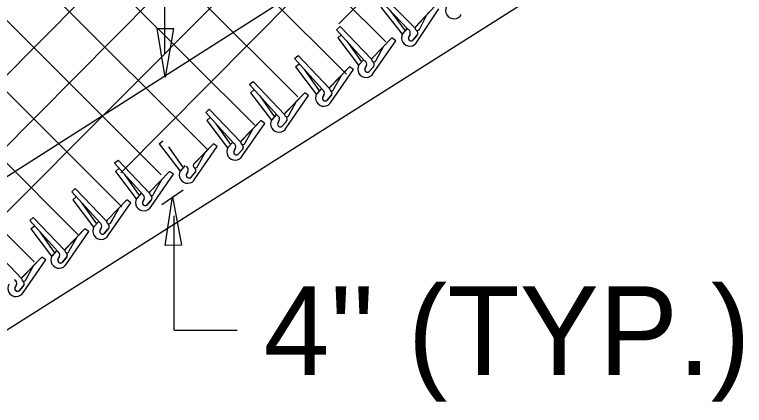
# Model space of a CAD drawing. Extents: x 0 to 2.85, y -0.1 to 1.83.
# Drawn here: x 1.6771 to 1.7594, y 1.3819 to 1.426 of the extents above; entities that cross this region are included whole.
import ezdxf

# ---------------------------------------------------------------- set-up
doc = ezdxf.new("R2010")
doc.units = 0
for name, color, linetype in [('CT_Dimensions', 7, 'Continuous'), ('sb_Chainlink Fence', 7, 'Continuous'), ('sb_Earth', 7, 'Continuous'), ('sb_Existing Structural Steel', 7, 'Continuous')]:
    doc.layers.add(name, color=color, linetype=linetype)

msp = doc.modelspace()

# ---------------------------------------------------------------- linework, layer by layer
at = {"layer": 'CT_Dimensions'}
for p, q in [((1.694051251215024, 1.4215621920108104), (1.694051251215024, 1.43019635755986)), ((1.6937099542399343, 1.404569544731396), (1.696140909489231, 1.4062363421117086)), ((1.6950964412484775, 1.390403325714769), (1.6950964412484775, 1.4033021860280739)), ((1.6950964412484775, 1.390403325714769), (1.702206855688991, 1.390403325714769))]:
    msp.add_line(p, q, dxfattribs=at)
for points in [[(1.6950225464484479, 1.4244544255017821), (1.6941064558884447, 1.4189578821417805), (1.6931903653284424, 1.4244544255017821)], [(1.694091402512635, 1.399944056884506), (1.6949236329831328, 1.4054539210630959), (1.6959233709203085, 1.3999719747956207)]]:
    msp.add_lwpolyline(points, close=True, dxfattribs=at)
at = {"layer": 'sb_Chainlink Fence'}
for p, q in [((1.6886284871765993, 1.4161145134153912), (1.9989168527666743, 1.728697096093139)), ((1.6483040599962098, 1.3830225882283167), (1.9873022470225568, 1.7249794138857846)), ((1.689092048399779, 1.4081735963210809), (1.9986754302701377, 1.720458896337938)), ((1.713665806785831, 1.4249653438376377), (1.998677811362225, 1.7124648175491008)), ((1.6649561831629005, 1.4078165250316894), (1.9657124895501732, 1.7111977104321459)), ((1.6426948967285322, 1.4992079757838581), (1.7189591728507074, 1.422943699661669)), ((1.6378194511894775, 1.4960224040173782), (1.714540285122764, 1.4193015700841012)), ((1.6330927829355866, 1.4926880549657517), (1.7090524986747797, 1.4167283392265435)), ((1.6282212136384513, 1.4894986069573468), (1.70419564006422, 1.4135241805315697)), ((1.623474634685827, 1.486184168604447), (1.6988537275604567, 1.4108050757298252)), ((1.6186308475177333, 1.4829669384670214), (1.6936570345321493, 1.4079407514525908)), ((1.6138328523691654, 1.4797039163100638), (1.6892080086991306, 1.404328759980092)), ((1.609050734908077, 1.4764250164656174), (1.6843031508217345, 1.4011726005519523)), ((1.604244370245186, 1.47317036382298), (1.6793177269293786, 1.3980970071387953)), ((1.7214957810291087, 1.4243386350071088), (1.7182739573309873, 1.4277686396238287)), ((1.7222936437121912, 1.4244802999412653), (1.7186701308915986, 1.428126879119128)), ((1.7184073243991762, 1.4268425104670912), (1.7208169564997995, 1.4238052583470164)), ((1.7245110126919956, 1.4269648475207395), (1.7223387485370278, 1.4246297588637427)), ((1.7245110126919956, 1.4269648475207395), (1.722352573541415, 1.4246434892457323)), ((1.7194459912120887, 1.4265093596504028), (1.7211406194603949, 1.4241976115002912)), ((1.7225162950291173, 1.4229733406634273), (1.7249566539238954, 1.426659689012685)), ((1.7227952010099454, 1.424428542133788), (1.7236084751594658, 1.4259792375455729)), ((1.7134325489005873, 1.4243088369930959), (1.7138360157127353, 1.4246588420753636)), ((1.7165830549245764, 1.4208132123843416), (1.7134325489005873, 1.4243088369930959)), ((1.7173836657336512, 1.4209384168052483), (1.7138360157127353, 1.4246588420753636)), ((1.7213541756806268, 1.4244253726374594), (1.7208624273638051, 1.4238465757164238)), ((1.7213607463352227, 1.4244343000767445), (1.7208649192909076, 1.4238486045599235)), ((1.713546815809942, 1.4233801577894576), (1.7139502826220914, 1.4237301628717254)), ((1.7208284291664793, 1.4237805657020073), (1.7207973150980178, 1.4237077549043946)), ((1.7208649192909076, 1.4238486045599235), (1.7208284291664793, 1.4237805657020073)), ((1.7215430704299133, 1.4234448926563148), (1.7217069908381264, 1.4237990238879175)), ((1.721706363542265, 1.4237864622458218), (1.7215434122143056, 1.4234529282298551)), ((1.7224694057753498, 1.4236421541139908), (1.7220237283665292, 1.4231155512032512)), ((1.7220648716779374, 1.423158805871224), (1.7224694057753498, 1.4236421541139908)), ((1.713546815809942, 1.4233801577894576), (1.715893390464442, 1.4202939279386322)), ((1.714578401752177, 1.4230256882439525), (1.7162250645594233, 1.4206795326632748)), ((1.7196517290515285, 1.4233767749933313), (1.717431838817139, 1.4210869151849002)), ((1.7196517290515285, 1.4233767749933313), (1.717445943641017, 1.421100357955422)), ((1.7175752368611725, 1.4194271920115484), (1.7200909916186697, 1.423062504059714)), ((1.7200909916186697, 1.423062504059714), (1.7196517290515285, 1.4233767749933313)), ((1.717884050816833, 1.4208763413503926), (1.718729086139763, 1.4224099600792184)), ((1.7086758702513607, 1.4210507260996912), (1.7090793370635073, 1.4214007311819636)), ((1.7118263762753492, 1.4175551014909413), (1.7086758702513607, 1.4210507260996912)), ((1.7126269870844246, 1.4176803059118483), (1.7090793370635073, 1.4214007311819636)), ((1.7087901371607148, 1.4201220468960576), (1.7091936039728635, 1.4204720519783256)), ((1.7159043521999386, 1.4202690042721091), (1.7158717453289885, 1.420196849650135)), ((1.7159422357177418, 1.4203362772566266), (1.7159043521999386, 1.4202690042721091)), ((1.7164432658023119, 1.420902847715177), (1.715939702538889, 1.4203343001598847)), ((1.7164500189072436, 1.4209116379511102), (1.7159422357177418, 1.4203362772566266)), ((1.7166119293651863, 1.419918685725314), (1.7167831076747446, 1.4202693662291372)), ((1.716782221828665, 1.4202568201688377), (1.7166124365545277, 1.4199267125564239)), ((1.7087901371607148, 1.4201220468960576), (1.7111367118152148, 1.4170358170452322)), ((1.7098217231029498, 1.4197675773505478), (1.711468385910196, 1.417421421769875)), ((1.7148950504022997, 1.4201186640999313), (1.7126751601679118, 1.4178288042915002)), ((1.7148950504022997, 1.4201186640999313), (1.7126892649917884, 1.417842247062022)), ((1.7128185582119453, 1.4161690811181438), (1.7153343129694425, 1.419804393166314)), ((1.7153343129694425, 1.419804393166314), (1.7148950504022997, 1.4201186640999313)), ((1.717542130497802, 1.4200968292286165), (1.7170857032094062, 1.4195795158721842)), ((1.7171277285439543, 1.4196219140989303), (1.717542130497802, 1.4200968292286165)), ((1.7131273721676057, 1.417618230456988), (1.7139724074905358, 1.4191518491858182)), ((1.6949879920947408, 1.4146492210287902), (1.6913644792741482, 1.418295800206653)), ((1.7036130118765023, 1.4181265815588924), (1.704016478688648, 1.4184765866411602)), ((1.7067635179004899, 1.4146309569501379), (1.7036130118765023, 1.4181265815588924)), ((1.7075641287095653, 1.4147561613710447), (1.704016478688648, 1.4184765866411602)), ((1.7037272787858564, 1.4171979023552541), (1.7041307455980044, 1.417547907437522)), ((1.7037272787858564, 1.4171979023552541), (1.7060738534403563, 1.4141116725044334)), ((1.7047588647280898, 1.4168434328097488), (1.7064055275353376, 1.4144972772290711)), ((1.709832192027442, 1.4171945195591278), (1.7076123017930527, 1.4149046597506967)), ((1.709832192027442, 1.4171945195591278), (1.70762640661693, 1.4149181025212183)), ((1.7077556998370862, 1.4132449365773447), (1.7102714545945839, 1.4168802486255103)), ((1.7102714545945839, 1.4168802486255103), (1.709832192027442, 1.4171945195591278)), ((1.7111476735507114, 1.4170108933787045), (1.7111150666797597, 1.4169387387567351)), ((1.7111855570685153, 1.4170781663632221), (1.7111476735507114, 1.4170108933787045)), ((1.711686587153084, 1.4176447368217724), (1.7111830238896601, 1.4170761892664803)), ((1.7116933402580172, 1.4176535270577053), (1.7111855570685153, 1.4170781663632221)), ((1.7118552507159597, 1.416660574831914), (1.7120264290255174, 1.417011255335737)), ((1.7120255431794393, 1.416998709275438), (1.7118557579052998, 1.416668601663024)), ((1.651649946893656, 1.3791359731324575), (1.6886284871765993, 1.4161145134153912)), ((1.7080645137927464, 1.4146940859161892), (1.7089095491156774, 1.4162277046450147)), ((1.7127854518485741, 1.4168387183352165), (1.712329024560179, 1.4163214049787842)), ((1.712371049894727, 1.4163638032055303), (1.7127854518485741, 1.4168387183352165)), ((1.6986729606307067, 1.4149767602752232), (1.6990764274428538, 1.415326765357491)), ((1.7026240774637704, 1.4116063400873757), (1.6990764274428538, 1.415326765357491)), ((1.701823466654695, 1.4114811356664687), (1.6986729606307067, 1.4149767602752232)), ((1.6987872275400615, 1.414048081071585), (1.6991906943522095, 1.414398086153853)), ((1.7066237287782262, 1.4147205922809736), (1.7061201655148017, 1.4141520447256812)), ((1.706630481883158, 1.4147293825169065), (1.7061226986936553, 1.4141540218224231)), ((1.6987872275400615, 1.414048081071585), (1.7011338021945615, 1.4109618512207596)), ((1.6998188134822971, 1.4136936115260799), (1.7014654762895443, 1.4113474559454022)), ((1.7048921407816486, 1.4140446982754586), (1.7026722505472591, 1.4117548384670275)), ((1.7048921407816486, 1.4140446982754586), (1.7026863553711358, 1.4117682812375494)), ((1.7028156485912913, 1.4100951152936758), (1.7053314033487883, 1.4137304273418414)), ((1.7053314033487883, 1.4137304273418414), (1.7048921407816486, 1.4140446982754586)), ((1.7060848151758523, 1.4140867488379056), (1.7060522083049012, 1.4140145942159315)), ((1.7061226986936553, 1.4141540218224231), (1.7060848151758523, 1.4140867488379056)), ((1.7067923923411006, 1.4137364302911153), (1.7069635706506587, 1.4140871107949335)), ((1.70696268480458, 1.4140745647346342), (1.7067928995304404, 1.4137444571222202)), ((1.7077225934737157, 1.413914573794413), (1.707266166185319, 1.4133972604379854)), ((1.7073081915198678, 1.4134396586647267), (1.7077225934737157, 1.413914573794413)), ((1.7031244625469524, 1.4115442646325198), (1.7039694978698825, 1.4130778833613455)), ((1.6934315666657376, 1.411432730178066), (1.6938350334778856, 1.411782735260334)), ((1.6934315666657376, 1.411432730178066), (1.6957781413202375, 1.4083465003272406)), ((1.699536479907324, 1.4114293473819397), (1.6973165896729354, 1.4091394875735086)), ((1.699536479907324, 1.4114293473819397), (1.6973306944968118, 1.4091529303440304)), ((1.6974599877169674, 1.4074797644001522), (1.6999757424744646, 1.4111150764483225)), ((1.6999757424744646, 1.4111150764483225), (1.699536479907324, 1.4114293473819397)), ((1.701683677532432, 1.4115707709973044), (1.7011801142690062, 1.411002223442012)), ((1.701690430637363, 1.4115795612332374), (1.7011826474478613, 1.4110042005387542)), ((1.6944631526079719, 1.4110782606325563), (1.696109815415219, 1.4087321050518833)), ((1.6977688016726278, 1.4089289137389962), (1.6986138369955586, 1.4104625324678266)), ((1.7011447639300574, 1.4109369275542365), (1.701112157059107, 1.4108647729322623)), ((1.7011826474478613, 1.4110042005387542), (1.7011447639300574, 1.4109369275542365)), ((1.7018523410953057, 1.4105866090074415), (1.7020235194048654, 1.4109372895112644)), ((1.7020226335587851, 1.410924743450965), (1.7018528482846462, 1.4105946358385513)), ((1.7027825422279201, 1.4107647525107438), (1.7023261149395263, 1.4102474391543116)), ((1.7023681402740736, 1.4102898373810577), (1.7027825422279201, 1.4107647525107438)), ((1.688377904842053, 1.4092434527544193), (1.688781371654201, 1.4095934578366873)), ((1.6923290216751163, 1.4058730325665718), (1.688781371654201, 1.4095934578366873)), ((1.6915284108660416, 1.4057478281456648), (1.688377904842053, 1.4092434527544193)), ((1.6884921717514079, 1.4083147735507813), (1.6888956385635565, 1.408664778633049)), ((1.6963280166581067, 1.4089554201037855), (1.6958244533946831, 1.4083868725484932)), ((1.6963347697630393, 1.4089642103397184), (1.6958269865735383, 1.4083888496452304)), ((1.6884921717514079, 1.4083147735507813), (1.6908387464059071, 1.4052285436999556)), ((1.6895237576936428, 1.4079603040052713), (1.69117042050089, 1.4056141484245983)), ((1.6945970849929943, 1.4083113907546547), (1.6923771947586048, 1.4060215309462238)), ((1.6945970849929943, 1.4083113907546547), (1.6923912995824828, 1.4060349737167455)), ((1.6925205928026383, 1.4043618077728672), (1.6950363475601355, 1.4079971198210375)), ((1.6950363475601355, 1.4079971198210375), (1.6945970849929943, 1.4083113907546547)), ((1.6957891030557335, 1.4083215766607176), (1.6957564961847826, 1.4082494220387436)), ((1.6958269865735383, 1.4083888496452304), (1.6957891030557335, 1.4083215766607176)), ((1.6964966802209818, 1.4079712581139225), (1.6966678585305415, 1.4083219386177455)), ((1.6966669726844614, 1.4083093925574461), (1.6964971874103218, 1.4079792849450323)), ((1.6974268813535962, 1.40814940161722), (1.6969704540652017, 1.4076320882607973)), ((1.6970124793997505, 1.4076744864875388), (1.6974268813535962, 1.40814940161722)), ((1.6928294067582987, 1.4058109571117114), (1.6936744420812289, 1.4073445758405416)), ((1.6835639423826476, 1.4060272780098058), (1.6839674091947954, 1.4063772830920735)), ((1.6875150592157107, 1.402656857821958), (1.6839674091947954, 1.4063772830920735)), ((1.6867144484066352, 1.4025316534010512), (1.6835639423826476, 1.4060272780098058)), ((1.6836782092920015, 1.4050985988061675), (1.684081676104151, 1.4054486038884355)), ((1.6913886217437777, 1.4058374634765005), (1.6908850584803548, 1.4052689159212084)), ((1.6913953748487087, 1.4058462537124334), (1.6908875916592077, 1.4052708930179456)), ((1.6836782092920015, 1.4050985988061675), (1.6860247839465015, 1.4020123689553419)), ((1.6847097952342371, 1.4047441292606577), (1.6863564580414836, 1.4023979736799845)), ((1.6897831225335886, 1.4050952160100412), (1.6875632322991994, 1.40280535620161)), ((1.6897831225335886, 1.4050952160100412), (1.6875773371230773, 1.4028187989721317)), ((1.6877066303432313, 1.4011456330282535), (1.6902223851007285, 1.404780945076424)), ((1.6902223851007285, 1.404780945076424), (1.6897831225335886, 1.4050952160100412)), ((1.6908497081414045, 1.4052036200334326), (1.6908171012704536, 1.4051314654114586)), ((1.6908875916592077, 1.4052708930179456), (1.6908497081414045, 1.4052036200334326)), ((1.6915572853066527, 1.4048533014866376), (1.691728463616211, 1.4052039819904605)), ((1.6917275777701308, 1.4051914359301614), (1.6915577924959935, 1.4048613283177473)), ((1.6924874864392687, 1.4050314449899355), (1.692031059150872, 1.4045141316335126)), ((1.6920730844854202, 1.4045565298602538), (1.6924874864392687, 1.4050314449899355)), ((1.6880154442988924, 1.4025947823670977), (1.6888604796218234, 1.4041284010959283)), ((1.6788312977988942, 1.4027651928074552), (1.6792347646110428, 1.403115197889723)), ((1.6827824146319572, 1.3993947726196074), (1.6792347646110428, 1.403115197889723)), ((1.6819818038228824, 1.3992695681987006), (1.6788312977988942, 1.4027651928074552)), ((1.6789455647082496, 1.401836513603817), (1.679349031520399, 1.4021865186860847)), ((1.6860736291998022, 1.4020547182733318), (1.686035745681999, 1.401987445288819)), ((1.6865746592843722, 1.402621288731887), (1.6860710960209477, 1.4020527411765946)), ((1.6865814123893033, 1.4026300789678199), (1.6860736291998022, 1.4020547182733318)), ((1.6789455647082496, 1.401836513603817), (1.681292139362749, 1.3987502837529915)), ((1.679977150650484, 1.4014820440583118), (1.6816238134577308, 1.3991358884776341)), ((1.685050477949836, 1.4018331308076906), (1.6828305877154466, 1.3995432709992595)), ((1.685050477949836, 1.4018331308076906), (1.6828446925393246, 1.3995567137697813)), ((1.6829739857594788, 1.3978835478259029), (1.685489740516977, 1.401518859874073)), ((1.685489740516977, 1.401518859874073), (1.685050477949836, 1.4018331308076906)), ((1.686035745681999, 1.401987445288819), (1.6860031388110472, 1.4019152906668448)), ((1.6867433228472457, 1.4016371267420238), (1.6869145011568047, 1.401987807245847)), ((1.6869136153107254, 1.4019752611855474), (1.6867438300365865, 1.4016451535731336)), ((1.6876735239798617, 1.4018152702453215), (1.6872170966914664, 1.4012979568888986)), ((1.6872591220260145, 1.40134035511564), (1.6876735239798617, 1.4018152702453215)), ((1.6832827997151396, 1.3993326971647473), (1.6841278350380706, 1.4008663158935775)), ((1.6779241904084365, 1.3961999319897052), (1.6743765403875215, 1.399920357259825)), ((1.6813409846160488, 1.398792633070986), (1.6813031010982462, 1.3987253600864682)), ((1.6818420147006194, 1.3993592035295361), (1.6813384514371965, 1.398790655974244)), ((1.6818487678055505, 1.3993679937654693), (1.6813409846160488, 1.398792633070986)), ((1.6801922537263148, 1.398638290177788), (1.6779723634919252, 1.3963484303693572)), ((1.6801922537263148, 1.398638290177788), (1.6779864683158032, 1.3963618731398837)), ((1.678115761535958, 1.3946887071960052), (1.6806315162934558, 1.3983240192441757)), ((1.6806315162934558, 1.3983240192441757), (1.6801922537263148, 1.398638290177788)), ((1.6813031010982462, 1.3987253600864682), (1.681270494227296, 1.3986532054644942)), ((1.6820106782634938, 1.3983750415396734), (1.682181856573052, 1.3987257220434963)), ((1.6821809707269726, 1.398713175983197), (1.6820111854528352, 1.3983830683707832)), ((1.682940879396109, 1.3985531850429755), (1.6824844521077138, 1.3980358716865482)), ((1.682526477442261, 1.3980782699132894), (1.682940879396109, 1.3985531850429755)), ((1.678424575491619, 1.3961378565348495), (1.6792696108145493, 1.3976714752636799)), ((1.6771524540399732, 1.3951802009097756), (1.6773236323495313, 1.3955308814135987)), ((1.6773227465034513, 1.3955183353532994), (1.677152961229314, 1.3951882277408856)), ((1.678082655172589, 1.3953583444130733), (1.6776262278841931, 1.394841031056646)), ((1.6776682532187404, 1.394883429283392), (1.678082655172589, 1.3953583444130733))]:
    msp.add_line(p, q, dxfattribs=at)
for centre, radius, start, end in [((1.7266479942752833, 1.4264741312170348), 0.0009354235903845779, 150.71281129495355, 333.6194641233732), ((1.7213194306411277, 1.4239587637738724), 0.0004188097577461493, 336.42296563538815, 65.09751420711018), ((1.7225432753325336, 1.4244729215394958), 0.0002558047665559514, 138.96114269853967, 350.00923971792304), ((1.7216782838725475, 1.423388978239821), 0.0009354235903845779, 150.71281129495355, 333.6194641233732), ((1.7218311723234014, 1.4233520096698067), 0.0003049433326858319, 160.6740382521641, 309.1570792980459), ((1.7218322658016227, 1.4233534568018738), 0.0003033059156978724, 162.454436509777, 320.07648952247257), ((1.7221997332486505, 1.4239252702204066), 0.00039099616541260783, 313.60686611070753, 52.174038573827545), ((1.7222102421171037, 1.423925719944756), 0.00038439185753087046, 320.1413408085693, 52.94493342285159), ((1.717633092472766, 1.4209258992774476), 0.00025580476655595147, 137.78116116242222, 348.8292581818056), ((1.7167459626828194, 1.4198599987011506), 0.0009354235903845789, 149.5328297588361, 332.4394825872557), ((1.7163989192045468, 1.4204370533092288), 0.0004188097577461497, 335.24298409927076, 63.917532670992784), ((1.7172783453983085, 1.4203854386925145), 0.0003909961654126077, 312.4268845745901, 50.99405703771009), ((1.7172888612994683, 1.4203856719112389), 0.0003843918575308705, 318.9613592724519, 51.76495188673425), ((1.7168980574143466, 1.4198198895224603), 0.0003049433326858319, 159.49405671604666, 307.97709776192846), ((1.7168991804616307, 1.4198213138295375), 0.0003033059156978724, 161.27445497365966, 318.89650798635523), ((1.7128764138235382, 1.4176677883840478), 0.00025580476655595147, 137.78116116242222, 348.8292581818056), ((1.7119892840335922, 1.4166018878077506), 0.0009354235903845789, 149.5328297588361, 332.4394825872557), ((1.7116422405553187, 1.417178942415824), 0.0004188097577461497, 335.24298409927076, 63.917532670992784), ((1.7125216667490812, 1.4171273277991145), 0.0003909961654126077, 312.4268845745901, 50.99405703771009), ((1.7125321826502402, 1.4171275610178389), 0.0003843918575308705, 318.9613592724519, 51.76495188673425), ((1.7121413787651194, 1.4165617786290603), 0.0003049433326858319, 159.49405671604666, 307.97709776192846), ((1.7121425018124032, 1.4165632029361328), 0.0003033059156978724, 161.27445497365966, 318.89650798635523), ((1.7065793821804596, 1.4142547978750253), 0.0004188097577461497, 335.24298409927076, 63.917532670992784), ((1.7078135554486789, 1.4147436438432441), 0.00025580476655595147, 137.78116116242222, 348.8292581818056), ((1.7074588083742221, 1.4142031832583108), 0.0003909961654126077, 312.4268845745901, 50.99405703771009), ((1.7074693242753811, 1.4142034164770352), 0.0003843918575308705, 318.9613592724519, 51.76495188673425), ((1.706926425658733, 1.4136777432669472), 0.0009354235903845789, 149.5328297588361, 332.4394825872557), ((1.7070785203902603, 1.4136376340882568), 0.0003049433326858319, 159.49405671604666, 307.97709776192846), ((1.7070796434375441, 1.4136390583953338), 0.0003033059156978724, 161.27445497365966, 318.89650798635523), ((1.701639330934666, 1.4111049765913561), 0.0004188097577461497, 335.24298409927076, 63.917532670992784), ((1.702873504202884, 1.411593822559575), 0.00025580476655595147, 137.78116116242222, 348.8292581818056), ((1.7025187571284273, 1.411053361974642), 0.0003909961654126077, 312.4268845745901, 50.99405703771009), ((1.7025292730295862, 1.4110535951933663), 0.0003843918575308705, 318.9613592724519, 51.76495188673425), ((1.7019863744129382, 1.410527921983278), 0.0009354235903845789, 149.5328297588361, 332.4394825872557), ((1.702138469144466, 1.4104878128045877), 0.0003049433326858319, 159.49405671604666, 307.97709776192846), ((1.7021395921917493, 1.4104892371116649), 0.0003033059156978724, 161.27445497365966, 318.89650798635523), ((1.6962836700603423, 1.4084896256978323), 0.0004188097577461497, 335.24298409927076, 63.917532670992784), ((1.6975178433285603, 1.4089784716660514), 0.00025580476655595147, 137.78116116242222, 348.8292581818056), ((1.6971630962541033, 1.4084380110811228), 0.0003909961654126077, 312.4268845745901, 50.99405703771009), ((1.6971736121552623, 1.4084382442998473), 0.0003843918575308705, 318.9613592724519, 51.76495188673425), ((1.6966307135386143, 1.407912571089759), 0.0009354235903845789, 149.5328297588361, 332.4394825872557), ((1.696782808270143, 1.4078724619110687), 0.0003049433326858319, 159.49405671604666, 307.97709776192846), ((1.6967839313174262, 1.4078738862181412), 0.0003033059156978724, 161.27445497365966, 318.89650798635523), ((1.6913442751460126, 1.4053716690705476), 0.0004188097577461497, 335.24298409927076, 63.917532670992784), ((1.6925784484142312, 1.4058605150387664), 0.00025580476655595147, 137.78116116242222, 348.8292581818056), ((1.692223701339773, 1.4053200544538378), 0.0003909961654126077, 312.4268845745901, 50.99405703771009), ((1.6922342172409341, 1.4053202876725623), 0.0003843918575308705, 318.9613592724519, 51.76495188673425), ((1.6916913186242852, 1.4047946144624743), 0.0009354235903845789, 149.5328297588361, 332.4394825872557), ((1.6918434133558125, 1.4047545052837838), 0.0003049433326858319, 159.49405671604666, 307.97709776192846), ((1.6918445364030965, 1.4047559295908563), 0.0003033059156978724, 161.27445497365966, 318.89650798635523), ((1.6868773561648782, 1.4015784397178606), 0.0009354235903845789, 149.5328297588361, 332.4394825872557), ((1.6865303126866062, 1.4021554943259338), 0.0004188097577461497, 335.24298409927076, 63.917532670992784), ((1.6877644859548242, 1.4026443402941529), 0.00025580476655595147, 137.78116116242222, 348.8292581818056), ((1.6874097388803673, 1.4021038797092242), 0.0003909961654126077, 312.4268845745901, 50.99405703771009), ((1.6874202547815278, 1.4021041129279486), 0.0003843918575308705, 318.9613592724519, 51.76495188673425), ((1.687029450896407, 1.4015383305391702), 0.0003049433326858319, 159.49405671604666, 307.97709776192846), ((1.6870305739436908, 1.4015397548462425), 0.0003033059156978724, 161.27445497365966, 318.89650798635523), ((1.682144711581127, 1.39831635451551), 0.0009354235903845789, 149.5328297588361, 332.4394825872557), ((1.6817976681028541, 1.3988934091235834), 0.0004188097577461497, 335.24298409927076, 63.917532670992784), ((1.683031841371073, 1.399382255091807), 0.00025580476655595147, 137.78116116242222, 348.8292581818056), ((1.682677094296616, 1.3988417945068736), 0.0003909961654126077, 312.4268845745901, 50.99405703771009), ((1.6826876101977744, 1.3988420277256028), 0.0003843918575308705, 318.9613592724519, 51.76495188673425), ((1.6822968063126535, 1.3982762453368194), 0.0003049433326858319, 159.49405671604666, 307.97709776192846), ((1.682297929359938, 1.3982776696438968), 0.0003033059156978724, 161.27445497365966, 318.89650798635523), ((1.6781736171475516, 1.3961874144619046), 0.00025580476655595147, 137.78116116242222, 348.8292581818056), ((1.6772864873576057, 1.3951215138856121), 0.0009354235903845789, 149.5328297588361, 332.4394825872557), ((1.6769394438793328, 1.3956985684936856), 0.0004188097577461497, 335.24298409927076, 63.917532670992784), ((1.6778188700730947, 1.395646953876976), 0.0003909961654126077, 312.4268845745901, 50.99405703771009), ((1.6778293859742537, 1.3956471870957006), 0.0003843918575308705, 318.9613592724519, 51.76495188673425), ((1.6774385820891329, 1.3950814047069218), 0.0003049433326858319, 159.49405671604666, 307.97709776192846), ((1.6774397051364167, 1.3950828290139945), 0.0003033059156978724, 161.27445497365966, 318.89650798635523)]:
    msp.add_arc(centre, radius, start, end, dxfattribs=at)
at = {"layer": 'sb_Earth'}
msp.add_line((1.5044215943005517, 1.2815901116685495), (1.7823218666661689, 1.4576319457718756), dxfattribs=at)
at = {"layer": 'sb_Existing Structural Steel'}
msp.add_line((1.5021906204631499, 1.296704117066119), (1.7742550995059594, 1.4702761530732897), dxfattribs=at)

# ---------------------------------------------------------------- texts
at = {"layer": 'CT_Dimensions'}
msp.add_text("4'' (TYP.)", height=0.01, dxfattribs=at).set_placement((1.705194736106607, 1.3853492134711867))

doc.saveas('drawing.dxf')
